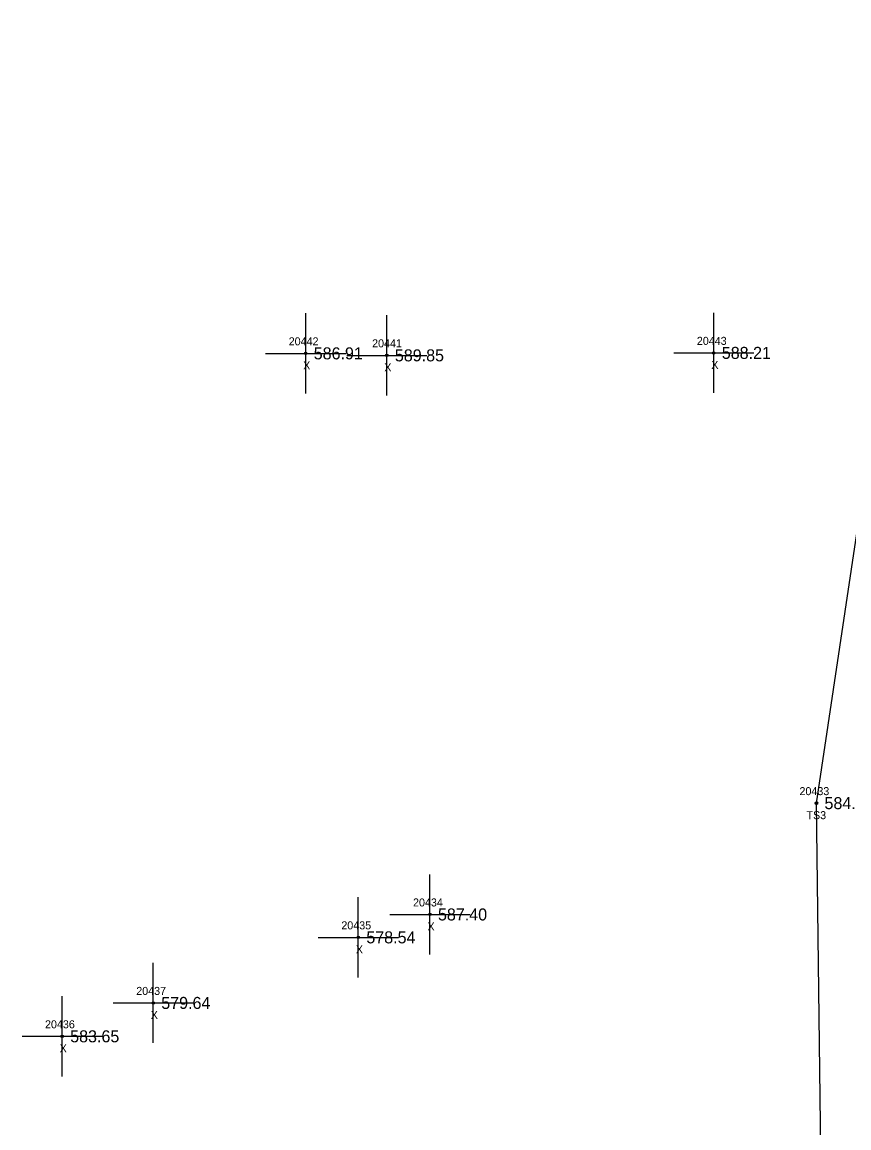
# Model space of a CAD drawing. Extents: x 1695443 to 1696344, y 1087542 to 1090645.
# Drawn here: x 1695592.6 to 1695695.8, y 1089395 to 1089533.1 of the extents above; entities that cross this region are included whole.
import ezdxf

# ---------------------------------------------------------------- set-up
doc = ezdxf.new("R2010")
doc.units = 0
for name, color, linetype in [('RD_DTM_BkLn2', 7, 'Continuous'), ('RD_DTM_BkLn_txCode', 7, 'Continuous'), ('RD_EX_Misc', 7, 'Continuous'), ('RD_EX_Misc_txCode', 7, 'Continuous'), ('RD_EX_TX_Misc_ELEV', 7, 'Continuous'), ('RD_SMD_Locator', 7, 'Continuous')]:
    doc.layers.add(name, color=color, linetype=linetype)

msp = doc.modelspace()

# ---------------------------------------------------------------- linework, layer by layer
at = {"layer": 'RD_DTM_BkLn2'}
msp.add_lwpolyline([(1695696.87, 1089328.65), (1695685.13, 1089358.98), (1695692.41, 1089382.13), (1695691.76, 1089435.56), (1695699.73, 1089488.72), (1695712.17, 1089543.62), (1695742.06, 1089638.06), (1695765.36, 1089733.76), (1695777.86, 1089780.36), (1695790.39, 1089828.61), (1695799.49, 1089874.59), (1695809.45, 1089923.14)], dxfattribs=at)
at = {"layer": 'RD_EX_Misc'}
for p, q in [((1695628, 1089486.74), (1695628, 1089496.74)), ((1695638.13, 1089486.49), (1695638.13, 1089496.49)), ((1695678.94, 1089486.8), (1695678.94, 1089496.8)), ((1695623, 1089491.74), (1695633, 1089491.74)), ((1695633.13, 1089491.49), (1695643.13, 1089491.49)), ((1695673.94, 1089491.8), (1695683.94, 1089491.8)), ((1695643.51, 1089416.66), (1695643.51, 1089426.66)), ((1695634.57, 1089413.8), (1695634.57, 1089423.8)), ((1695638.51, 1089421.66), (1695648.51, 1089421.66)), ((1695629.57, 1089418.8), (1695639.57, 1089418.8)), ((1695608.97, 1089405.61), (1695608.97, 1089415.61)), ((1695597.6, 1089401.44), (1695597.6, 1089411.44)), ((1695603.97, 1089410.61), (1695613.97, 1089410.61)), ((1695592.6, 1089406.44), (1695602.6, 1089406.44))]:
    msp.add_line(p, q, dxfattribs=at)
at = {"layer": 'RD_SMD_Locator'}
for centre in [(1695628, 1089491.74), (1695638.13, 1089491.49), (1695678.94, 1089491.8), (1695691.76, 1089435.56), (1695643.51, 1089421.66), (1695634.57, 1089418.8), (1695608.97, 1089410.61), (1695597.6, 1089406.44)]:
    msp.add_circle(centre, 0.15, dxfattribs=at)

# ---------------------------------------------------------------- texts
at = {"layer": 'RD_DTM_BkLn_txCode'}
for s, p in [('20433', (1695689.64, 1089436.56)), ('TS3', (1695690.51, 1089433.56))]:
    msp.add_text(s, height=1, dxfattribs=at).set_placement(p)
at = {"layer": 'RD_EX_Misc_txCode'}
for s, p in [('20442', (1695625.88, 1089492.74)), ('20443', (1695676.83, 1089492.8)), ('20441', (1695636.29, 1089492.49)), ('X', (1695627.68, 1089489.74)), ('X', (1695637.81, 1089489.49)), ('X', (1695678.63, 1089489.8)), ('20434', (1695641.4, 1089422.66)), ('20435', (1695632.45, 1089419.8)), ('X', (1695643.2, 1089419.66)), ('X', (1695634.26, 1089416.8)), ('20437', (1695606.85, 1089411.61)), ('X', (1695608.66, 1089408.61)), ('20436', (1695595.46, 1089407.44)), ('X', (1695597.29, 1089404.44))]:
    msp.add_text(s, height=1, dxfattribs=at).set_placement(p)
at = {"layer": 'RD_EX_TX_Misc_ELEV'}
for s, p in [('586.91', (1695629, 1089490.99)), ('589.85', (1695639.13, 1089490.74)), ('588.21', (1695679.94, 1089491.05)), ('584.62', (1695692.76, 1089434.81)), ('587.40', (1695644.51, 1089420.91)), ('578.54', (1695635.57, 1089418.05)), ('579.64', (1695609.97, 1089409.86)), ('583.65', (1695598.6, 1089405.69))]:
    msp.add_text(s, height=1.5, dxfattribs=at).set_placement(p)

doc.saveas('drawing.dxf')
